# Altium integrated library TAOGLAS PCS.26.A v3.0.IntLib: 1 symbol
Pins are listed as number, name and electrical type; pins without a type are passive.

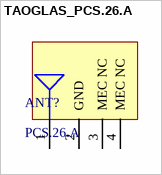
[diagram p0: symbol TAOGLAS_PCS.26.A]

## TAOGLAS_PCS.26.A
designator ANT?, comment PCS.26.A
Low Profile 4G LTE / NTN SMD Dielectric Antenna; ComponentLibStatus: Created; MFG: Taoglas; Temp_High: +85C; Temp_Low: -40C
footprint TAOGLAS_PCS.26.A (Low Profile 4G LTE / NTN SMD Dielectric Antenna)
pins: 1 RF FEED, 2 GND, 3 MEC NC, 4 MEC NC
